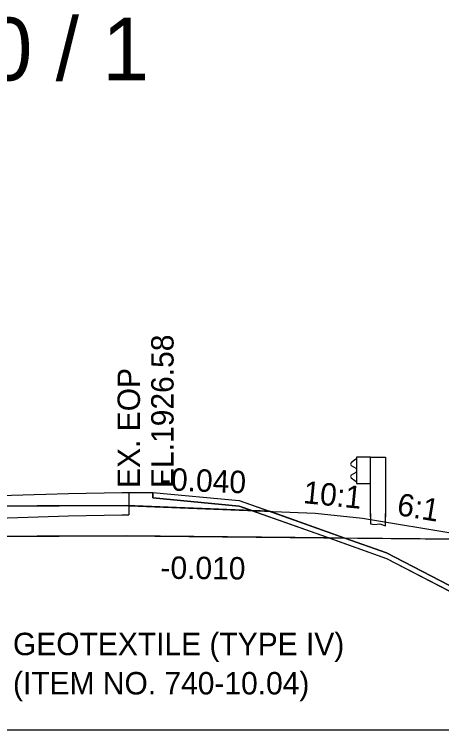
# Model space of a CAD drawing. Extents: x 1574 to 14903, y 7971 to 16537.
# Drawn here: x 4807 to 4826.07, y 9500 to 9531.89 of the extents above; entities that cross this region are included whole.
import ezdxf

# ---------------------------------------------------------------- set-up
doc = ezdxf.new("R2010")
doc.units = 0
for name, color, linetype in [('DESIGN - EARTHWORK - Shapes', 7, 'Continuous'), ('DESIGN - SHEET - Light Grid', 7, 'Continuous'), ('DESIGN - TYPICAL - Finished Grade and Subgrade', 7, 'Continuous'), ('DESIGN - TYPICAL - Finished Grade Slopes Text', 7, 'Continuous'), ('DESIGN - TYPICAL - Guardrail', 7, 'Continuous'), ('DESIGN - TYPICAL - Slope Tie Text', 7, 'Continuous'), ('DESIGN - TYPICAL - Subgrade Cross Slope Text', 7, 'Continuous'), ('SURVEY - GROUND - Bottom of Topsoil Layer', 7, 'Continuous'), ('SURVEY - GROUND - Existing Pavement Layer', 7, 'Continuous'), ('SURVEY - GROUND - Existing Pavement Text', 7, 'Continuous'), ('SURVEY - GROUND - Top of Ground', 7, 'Continuous')]:
    doc.layers.add(name, color=color, linetype=linetype)

msp = doc.modelspace()

# ---------------------------------------------------------------- linework, layer by layer
at = {"layer": 'DESIGN - EARTHWORK - Shapes'}
for points in [[(4788, 9509.708), (4787.313, 9509.68), (4788.999, 9509.825), (4789.422, 9509.859), (4791.086, 9509.907), (4799.729, 9510.25), (4809.421, 9510.528), (4811.802, 9510.572), (4812.105, 9510.576), (4813.175, 9510.582), (4813.175, 9510.332), (4817.032, 9509.971), (4817.595, 9509.771), (4812, 9509.995), (4804, 9509.964), (4800, 9509.948), (4796, 9509.868)], [(4817.032, 9510.221), (4818.387, 9509.739), (4817.595, 9509.771), (4817.032, 9509.971), (4813.175, 9510.332), (4813.175, 9510.582)], [(4817.595, 9509.771), (4820.952, 9508.578), (4821.029, 9508.551), (4812.005, 9508.641), (4804.005, 9508.609), (4800.017, 9508.594), (4796.027, 9508.514), (4788.027, 9508.354), (4772.344, 9508.04), (4772.344, 9508.825), (4773.628, 9508.844), (4780.067, 9509.251), (4786.017, 9509.577), (4787.147, 9509.666), (4787.313, 9509.68), (4788, 9509.708), (4796, 9509.868), (4800, 9509.948), (4804, 9509.964), (4812, 9509.995)], [(4817.595, 9509.771), (4820.952, 9508.578), (4821.029, 9508.551), (4821.749, 9508.543), (4820.952, 9508.828), (4818.387, 9509.739)], [(4821.029, 9508.551), (4823.604, 9507.63), (4828.802, 9504.942), (4835.482, 9501.482), (4836.367, 9501.344), (4841.481, 9500.776), (4843.349, 9500.792), (4843.349, 9501.042), (4841.481, 9501.026), (4836.367, 9501.594), (4835.482, 9501.732), (4831.104, 9504), (4828.802, 9505.192), (4823.604, 9507.88), (4821.749, 9508.543)], [(4828.802, 9505.192), (4831.104, 9504), (4837.432, 9504), (4828.48, 9508.476), (4821.749, 9508.543), (4823.604, 9507.88)]]:
    msp.add_lwpolyline(points, close=True, dxfattribs=at)
at = {"layer": 'DESIGN - SHEET - Light Grid'}
msp.add_line((4800, 9500), (5100, 9500), dxfattribs=at)
at = {"layer": 'DESIGN - TYPICAL - Finished Grade and Subgrade'}
for p, q in [((4804, 9509.964), (4811.767, 9509.994)), ((4811.767, 9509.994), (4820.417, 9509.648)), ((4820.417, 9509.648), (4822.531, 9509.437)), ((4822.531, 9509.437), (4828.304, 9508.474)), ((4804.005, 9508.609), (4811.767, 9508.64)), ((4811.767, 9508.64), (4828.304, 9508.474))]:
    msp.add_line(p, q, dxfattribs=at)
at = {"layer": 'DESIGN - TYPICAL - Guardrail'}
for p, q in [((4822.899, 9512.149), (4822.274, 9512.149)), ((4822.274, 9512.149), (4822.274, 9510.982)), ((4822.899, 9509.493), (4822.899, 9512.149)), ((4822.899, 9512.149), (4823.566, 9512.149)), ((4823.566, 9512.149), (4823.566, 9509.493)), ((4822.037, 9511.9), (4822.003, 9511.842)), ((4822.003, 9511.842), (4822.037, 9511.783)), ((4822.191, 9512.026), (4822.037, 9511.9)), ((4822.274, 9512.076), (4822.191, 9512.026)), ((4822.037, 9511.783), (4822.241, 9511.666)), ((4822.241, 9511.666), (4822.274, 9511.607)), ((4822.274, 9511.524), (4822.241, 9511.466)), ((4822.274, 9511.607), (4822.274, 9511.566)), ((4822.274, 9511.566), (4822.274, 9511.524)), ((4822.037, 9511.348), (4822.003, 9511.29)), ((4822.003, 9511.29), (4822.037, 9511.231)), ((4822.241, 9511.466), (4822.037, 9511.348)), ((4822.037, 9511.231), (4822.191, 9511.105)), ((4822.191, 9511.105), (4822.274, 9511.055)), ((4822.274, 9510.982), (4822.899, 9510.982)), ((4822.9, 9509.644), (4822.9, 9509.184)), ((4823.566, 9509.084), (4823.566, 9509.644)), ((4822.9, 9509.184), (4823.066, 9509.144)), ((4823.066, 9509.144), (4823.316, 9509.184)), ((4823.316, 9509.184), (4823.566, 9509.084))]:
    msp.add_line(p, q, dxfattribs=at)
at = {"layer": 'SURVEY - GROUND - Bottom of Topsoil Layer'}
for p, q in [((4813.175, 9510.332), (4813.175, 9510.582)), ((4813.175, 9510.332), (4817.032, 9509.971)), ((4817.032, 9509.971), (4820.952, 9508.578)), ((4820.952, 9508.578), (4823.604, 9507.63)), ((4823.604, 9507.63), (4828.802, 9504.942))]:
    msp.add_line(p, q, dxfattribs=at)
at = {"layer": 'SURVEY - GROUND - Existing Pavement Layer'}
for p, q in [((4812.105, 9510.576), (4812.105, 9509.576)), ((4799.729, 9509.25), (4809.421, 9509.528)), ((4809.421, 9509.528), (4811.802, 9509.572)), ((4811.802, 9509.572), (4812.105, 9509.576))]:
    msp.add_line(p, q, dxfattribs=at)
at = {"layer": 'SURVEY - GROUND - Top of Ground'}
msp.add_lwpolyline([(4758.774, 9508.617), (4773.628, 9508.844), (4780.067, 9509.251), (4786.017, 9509.577), (4787.147, 9509.666), (4788.999, 9509.825), (4789.422, 9509.859), (4791.086, 9509.907), (4799.729, 9510.25), (4809.421, 9510.528), (4811.802, 9510.572), (4812.105, 9510.576), (4813.175, 9510.582), (4817.032, 9510.221), (4820.952, 9508.828), (4823.604, 9507.88), (4828.802, 9505.192), (4835.482, 9501.732), (4836.367, 9501.594), (4841.481, 9501.026), (4846.481, 9501.067), (4849.602, 9500.848), (4852.681, 9500.922)], dxfattribs=at)

# ---------------------------------------------------------------- texts
at = {"layer": 'DESIGN - SHEET - Light Grid'}
msp.add_text('209+50.00 / 1', height=2.8, dxfattribs=at).set_placement((4790, 9528.945))
at = {"layer": 'DESIGN - TYPICAL - Finished Grade Slopes Text'}
for s, rotation, p in [('-0.040', 357.7094, (4813.53, 9510.684)), ('10:1', 354.2894, (4819.861, 9510.104)), ('6:1', 350.5377, (4824.033, 9509.575))]:
    msp.add_text(s, height=1, rotation=rotation, dxfattribs=at).set_placement(p)
at = {"layer": 'DESIGN - TYPICAL - Slope Tie Text'}
for s, p in [('GEOTEXTILE (TYPE IV)', (4806.937, 9503.322)), ('(ITEM NO. 740-10.04)', (4806.937, 9501.572))]:
    msp.add_text(s, height=1, rotation=360, dxfattribs=at).set_placement(p)
at = {"layer": 'DESIGN - TYPICAL - Subgrade Cross Slope Text'}
msp.add_text('-0.010', height=1, rotation=359.4271, dxfattribs=at).set_placement((4813.517, 9506.73))
at = {"layer": 'SURVEY - GROUND - Existing Pavement Text'}
for s, p in [('EL.1926.58', (4814.105, 9510.776)), ('EX. EOP', (4812.605, 9510.776))]:
    msp.add_text(s, height=1, rotation=90, dxfattribs=at).set_placement(p)

doc.saveas('drawing.dxf')
